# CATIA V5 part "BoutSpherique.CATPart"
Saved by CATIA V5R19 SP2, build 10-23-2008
Part number: BoutSpherique
Definition: NONE
Nomenclature: 1
Source: Unknown
Description: PART-1-DESC
Bounding box of the stored display mesh (mm): x 0 to 25.9, y -3 to 3, z -2.853 to 2.853
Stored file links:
  D:\SCHOOL\FRANCE\BANC_POUTRE_EN_MOUSSE\BoutSpherique.CATPart
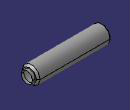
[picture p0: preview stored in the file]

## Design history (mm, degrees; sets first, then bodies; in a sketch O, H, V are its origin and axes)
Set1
  DatumSurface1 "CLOSED_SHELL #391"
Body1 (main body)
